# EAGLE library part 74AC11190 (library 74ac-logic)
Synchronous 4-bit up down decade COUNTER
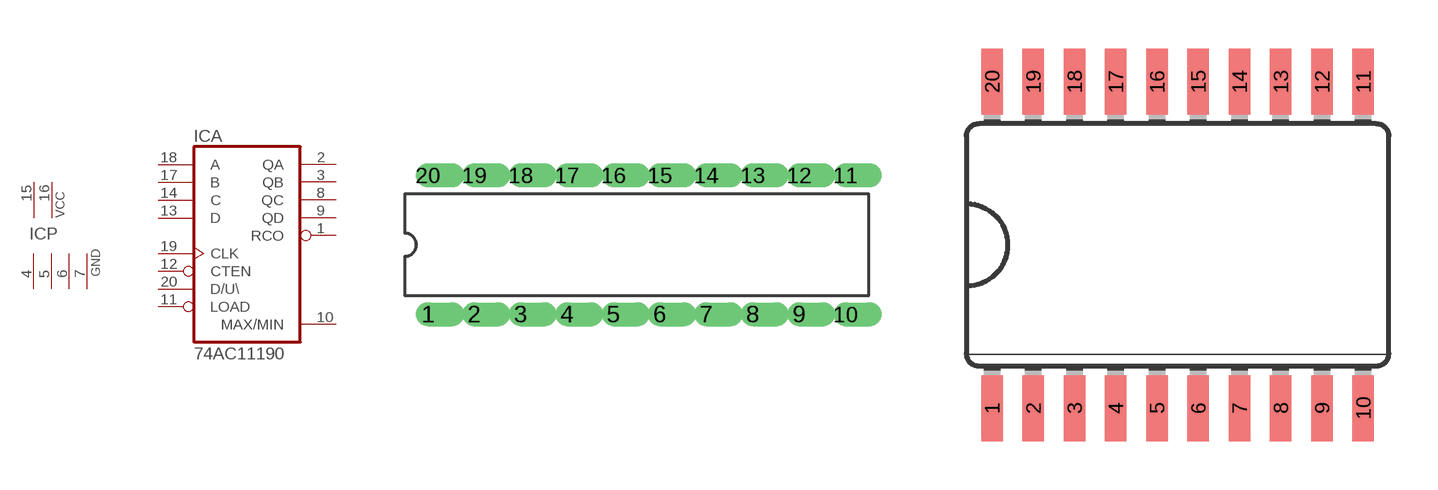
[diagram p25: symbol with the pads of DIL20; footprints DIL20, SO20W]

Designator prefix IC; gates A=7411190 P=2PWR4GND

## 74AC11190  [DIL20]
1  A:RCO  out
2  A:QA  out
3  A:QB  out
4  P:GND  pwr
5  P:GND  pwr
6  P:GND  pwr
7  P:GND  pwr
8  A:QC  out
9  A:QD  out
10  A:MAX/MIN  out
11  A:LOAD  in
12  A:CTEN  in
13  A:D  in
14  A:C  in
15  P:VCC  pwr
16  P:VCC  pwr
17  A:B  in
18  A:A  in
19  A:CLK  in
20  A:D/U\  in

## 74AC11190D  [SO20W]
Pads as for DIL20

## Footprint DIL20 (pad centres in mm)
Dual In Line
drill 0.813 offset: 1 -11.43,-3.81; 2 -8.89,-3.81; 3 -6.35,-3.81; 4 -3.81,-3.81; 5 -1.27,-3.81; 6 1.27,-3.81; 7 3.81,-3.81; 8 6.35,-3.81; 9 8.89,-3.81; 10 11.43,-3.81; 11 11.43,3.81; 12 8.89,3.81; 13 6.35,3.81; 14 3.81,3.81; 15 1.27,3.81; 16 -1.27,3.81; 17 -3.81,3.81; 18 -6.35,3.81; 19 -8.89,3.81; 20 -11.43,3.81

## Footprint SO20W (pad centres in mm)
Wide Small Outline package 300 mil
smd 0.66 x 2.032: 1 -5.715,-5.029; 2 -4.445,-5.029; 3 -3.175,-5.029; 4 -1.905,-5.029; 5 -0.635,-5.029; 6 0.635,-5.029; 7 1.905,-5.029; 8 3.175,-5.029; 9 4.445,-5.029; 10 5.715,-5.029; 11 5.715,5.029; 12 4.445,5.029; 13 3.175,5.029; 14 1.905,5.029; 15 0.635,5.029; 16 -0.635,5.029; 17 -1.905,5.029; 18 -3.175,5.029; 19 -4.445,5.029; 20 -5.715,5.029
